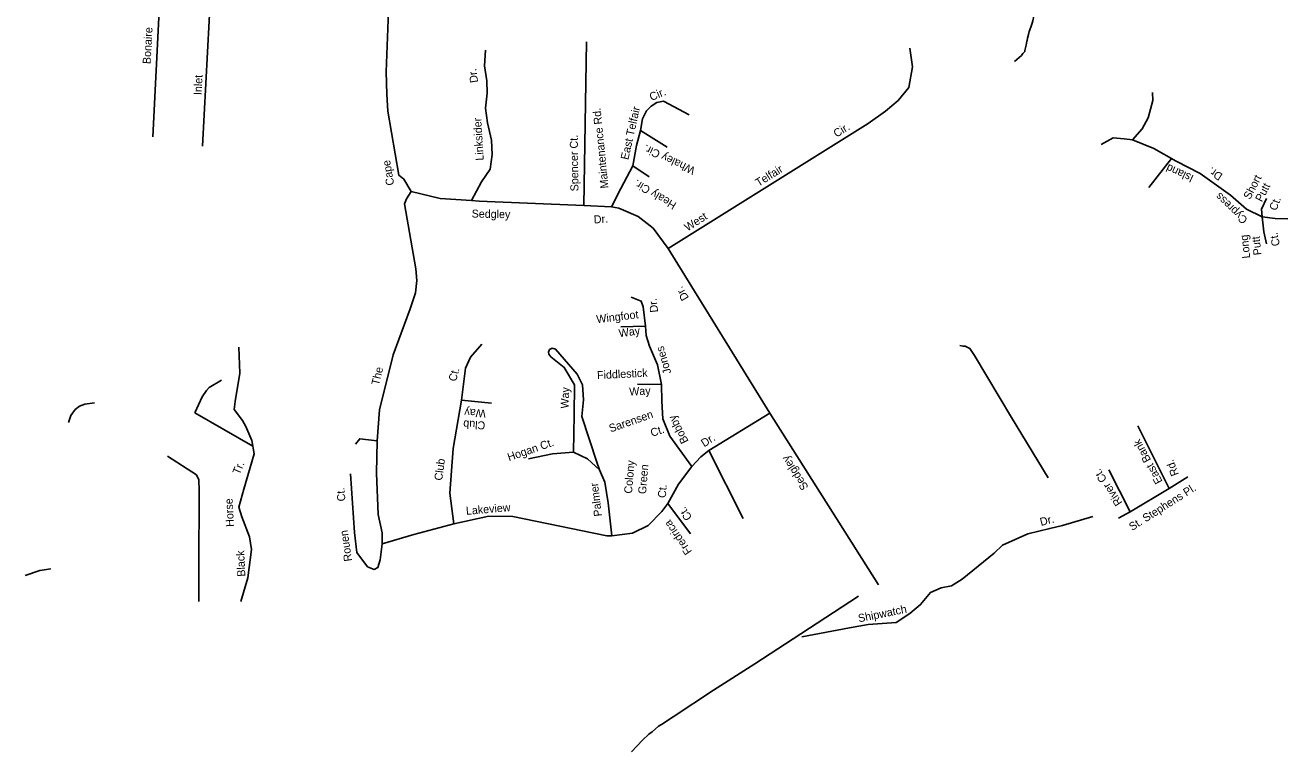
# Model space of a CAD drawing. Extents: x 2308163 to 2335412, y -96774 to 125428.
# Drawn here: x 2321552 to 2322199, y 33437 to 33809 of the extents above; entities that cross this region are included whole.
import ezdxf

# ---------------------------------------------------------------- set-up
doc = ezdxf.new("R2010")
doc.units = 0
doc.layers.add('Old_Level_10', color=7, linetype='Continuous')
doc.layers.add('Old_Level_35', color=7, linetype='Continuous')

msp = doc.modelspace()

# ---------------------------------------------------------------- linework, layer by layer
at = {"layer": 'Old_Level_35'}
for points in [[(2321642.5, 33747.31), (2321646.65, 33827.81), (2321648.99, 33855.68), (2321649.06, 33884.54), (2321651.46, 33914.24), (2321649.24, 33942.73), (2321649.43, 33961.51), (2321654.1, 33977.38), (2321655.96, 33991.52), (2321656.22, 34012.13)], [(2321616.99, 33752.13), (2321628.75, 33986.96), (2321626.26, 34007.67)], [(2321749.41, 33724.04), (2321745.7, 33730.45), (2321743.15, 33732.37), (2321737.47, 33765.29), (2321736.99, 33773.95), (2321736.6, 33785.48), (2321737.52, 33812.15), (2321737.23, 33818.97), (2321736.24, 33835.76), (2321735.15, 33849.93), (2321735.68, 33857.51), (2321738.55, 33865), (2321744.59, 33872.91), (2321749.05, 33880.61), (2321753.08, 33891.2), (2321757.94, 33910.41), (2321762.81, 33930.14), (2321769.45, 33955.57), (2321775.01, 33979.99), (2321776.9, 33993.77)], [(2322065.1, 33801.57), (2322065.4, 33802.63), (2322065.82, 33804.5), (2322066.22, 33806.12), (2322067.03, 33808.34), (2322067.72, 33810.45), (2322068.12, 33811.58), (2322068.26, 33812.44), (2322068.4, 33813.18), (2322068.29, 33814.31), (2322068.45, 33815.56), (2322067.95, 33820.45), (2322067.15, 33828.73), (2322066.12, 33838.01), (2322065.7, 33841.15), (2322065.68, 33845.27), (2322065.55, 33850.14), (2322065.86, 33858.26), (2322066.29, 33871.01), (2322067.1, 33889.12), (2322067.59, 33901.88)], [(2322058.61, 33790.79), (2322062.18, 33793.82), (2322062.96, 33794.81), (2322063.59, 33795.55), (2322063.98, 33795.9), (2322063.99, 33796.41), (2322064.58, 33799.14), (2322064.98, 33801.13), (2322065.1, 33801.57)], [(2321787.49, 33796.55), (2321786.95, 33788.46), (2321788.26, 33780.82), (2321788.3, 33774.53), (2321787.51, 33766.71), (2321788.57, 33759.34), (2321790.61, 33750.37), (2321790.89, 33743.03), (2321789.84, 33735.47), (2321785.43, 33729.08), (2321780.38, 33719.46)], [(2321837.88, 33716.95), (2321839.25, 33800.84)], [(2321881.13, 33694.78), (2321983.68, 33758.95), (2321992.54, 33765.19), (2321999.02, 33770.72), (2322004.49, 33777.34), (2322006.43, 33788.01), (2322004.92, 33797.48)], [(2321852, 33716.21), (2321856.78, 33725.62), (2321862.94, 33737.19), (2321864.87, 33747.6), (2321866.97, 33755.38), (2321867.97, 33761.37), (2321869.94, 33765.49), (2321872.38, 33767.76), (2321875.33, 33769.75), (2321878.76, 33770.42), (2321891.88, 33763.42)], [(2322119.09, 33750.47), (2322124.06, 33756.13), (2322127.18, 33761.86), (2322129.61, 33770.79), (2322129.48, 33774.77)], [(2321866.97, 33755.38), (2321880.56, 33746.79)], [(2322103.08, 33748.1), (2322109.31, 33751.6), (2322114.86, 33751.14), (2322119.09, 33750.47), (2322130.08, 33746.11), (2322141.54, 33739.61), (2322153.8, 33733.36), (2322169.34, 33722.21), (2322177.58, 33715.03), (2322185.67, 33711.04), (2322185.28, 33715.03), (2322187.86, 33720.51)], [(2321862.94, 33737.19), (2321871.4, 33731.66)], [(2322127.53, 33726.04), (2322139.05, 33741.03)], [(2321749.41, 33724.04), (2321746.92, 33720.25), (2321746.05, 33717.66), (2321751.72, 33684.48), (2321752.29, 33678.44), (2321751.55, 33672.18), (2321748.91, 33663.89), (2321740.24, 33640.37), (2321733.24, 33612.12), (2321731.9, 33596.2), (2321731.6, 33579.72), (2321732.44, 33558.48), (2321734.47, 33548.99), (2321734.54, 33543.49), (2321733.47, 33535.15), (2321732.28, 33531.26), (2321730.42, 33530.28), (2321727.06, 33531.7), (2321721.55, 33538.96), (2321720.33, 33549.21), (2321718.22, 33579.39)], [(2321893.25, 33582.99), (2321897.88, 33588.07), (2321901.92, 33591.33), (2321933.24, 33610.41), (2321881.13, 33694.78), (2321873.37, 33705.26), (2321865.71, 33711.28), (2321855.91, 33715.55), (2321852, 33716.21), (2321837.88, 33716.95), (2321784.3, 33719.06), (2321780.38, 33719.46), (2321764.17, 33720.54), (2321749.41, 33724.04)], [(2322185.67, 33711.04), (2322186.47, 33703.32), (2322187.85, 33697.17)], [(2322185.67, 33711.04), (2322192.28, 33710.28), (2322198.72, 33710.01)], [(2321734.54, 33543.49), (2321750.68, 33548.17), (2321771.31, 33553.74), (2321789.26, 33557.57), (2321801.57, 33557.41), (2321837.21, 33550.1), (2321849.69, 33547.58), (2321852.31, 33547.49), (2321862.84, 33548.96), (2321870.84, 33552.87), (2321877.89, 33559.96), (2321880.91, 33564.04), (2321886.4, 33574.06), (2321893.25, 33582.99), (2321882, 33598.56), (2321878.38, 33607.59), (2321877.9, 33616.51), (2321877.68, 33625.15), (2321875.67, 33635.17), (2321871.54, 33644.74), (2321869.9, 33650.29), (2321869.54, 33655.02), (2321868.31, 33665.01), (2321867.36, 33667.92), (2321862.19, 33669.93)], [(2321869.54, 33655.02), (2321856.95, 33654.67)], [(2321771.31, 33553.74), (2321769.28, 33569.36), (2321770.86, 33592.34), (2321775.12, 33617.07), (2321777.26, 33633.49), (2321779.81, 33639.16), (2321785.54, 33645.77)], [(2321662.08, 33513.8), (2321665.72, 33525.93), (2321667.6, 33540.53), (2321666.45, 33546.98), (2321662.67, 33557.19), (2321661.01, 33562.29), (2321663.62, 33571.36), (2321668.83, 33589.51), (2321667.69, 33596.42), (2321664.62, 33603.63), (2321663, 33606.66), (2321658.61, 33612.31), (2321659.21, 33616.42), (2321661.55, 33631), (2321661.09, 33644.3)], [(2321832.62, 33590.47), (2321833.02, 33609.57), (2321833.03, 33625.02), (2321827.83, 33633.84), (2321820.95, 33639.31), (2321819.95, 33640.65), (2321819.72, 33641.71), (2321820.29, 33643), (2321821.62, 33643.74), (2321823.44, 33643.15), (2321834.53, 33630.47), (2321837.22, 33624.87), (2321837.74, 33617.26), (2321836.92, 33608.65), (2321844.5, 33585.35), (2321845.93, 33581.38)], [(2322075.85, 33577.27), (2322057.2, 33608.23), (2322038.09, 33639.95), (2322035.79, 33643.65), (2322034.8, 33644.15), (2322033.45, 33644.68), (2322032.2, 33644.84), (2322030.58, 33645.14)], [(2321638.5, 33610.65), (2321642.3, 33618.72), (2321644.5, 33621.98), (2321645.81, 33623.61), (2321652.12, 33627.33)], [(2321877.68, 33625.15), (2321865.37, 33625.32)], [(2321573.79, 33605.57), (2321574.96, 33609.18), (2321577.19, 33612.29), (2321579.44, 33613.94), (2321582.15, 33615.1), (2321587.03, 33615.72)], [(2321775.12, 33617.07), (2321790.52, 33615.49)], [(2321638.5, 33610.65), (2321668.17, 33593.52)], [(2321933.24, 33610.41), (2321988.87, 33522.43)], [(2322121.84, 33603.92), (2322137.98, 33571.8), (2322147.48, 33577.84)], [(2321731.9, 33596.2), (2321723.03, 33597.29), (2321720.84, 33594.49)], [(2321624.45, 33588.42), (2321639.35, 33578.84), (2321640.52, 33576.25), (2321640.75, 33570.71), (2321640.62, 33530.74), (2321640.6, 33513.87)], [(2321852.31, 33547.49), (2321850.33, 33564.47), (2321848.6, 33575), (2321845.93, 33581.38), (2321839.84, 33587.08), (2321832.62, 33590.47), (2321821.85, 33589.54), (2321809.45, 33587.08)], [(2321901.92, 33591.33), (2321919.58, 33556.43)], [(2322117.92, 33559.76), (2322106.99, 33581.35)], [(2322137.98, 33571.8), (2322117.92, 33559.76), (2322111.97, 33556.52)], [(2321880.91, 33564.04), (2321892.59, 33548.46)], [(2321949.68, 33495.81), (2321974.04, 33500.27), (2321983.65, 33502.06), (2321998.02, 33503.16), (2322005.08, 33507.69), (2322010.55, 33512.27), (2322015.54, 33518.47), (2322021.04, 33520.93), (2322026.38, 33521.81), (2322031.81, 33525.33), (2322048.19, 33538.56), (2322052.57, 33542.65), (2322065.52, 33548.57), (2322076.76, 33551.36), (2322083.18, 33552.73), (2322098.74, 33557.5)], [(2321551.57, 33527.19), (2321558.97, 33529.79), (2321564.69, 33530.54)], [(2321978.76, 33516.57), (2321949.16, 33497.23), (2321925.52, 33481.93), (2321904.43, 33468.32), (2321883.72, 33454.68), (2321877.63, 33450.7), (2321876.22, 33449.85), (2321872.91, 33447.07), (2321871.24, 33445.85), (2321867.91, 33442.68), (2321862.35, 33436.81)]]:
    msp.add_lwpolyline(points, dxfattribs=at)

# ---------------------------------------------------------------- texts
at = {"layer": 'Old_Level_10'}
for s, rotation, p in [('Bonaire', 86.85287, (2321615.8, 33789.32)), ('Inlet', 87.81616, (2321642.04, 33773.44)), ('Dr.', 98.31149, (2321783.74, 33780.09)), ('Cir.', 22.8854, (2321872.55, 33770.41)), ('Maintenance Rd.', 95.70483, (2321850.57, 33725.84)), ('East Telfair ', 77.27677, (2321860.67, 33740.05)), ('Linksider', 93.46845, (2321786.6, 33740.04)), ('Cir.', 31.76923, (2321967.43, 33751.64)), ('Spencer Ct.', 90.73245, (2321835.14, 33724.16)), ('Whaley Cir.', 154.835, (2321895.36, 33736.21)), ('Cape', 99.96283, (2321740.76, 33727.52)), ('Telfair', 31.80691, (2321927.43, 33726.44)), (' Island ', 155.20343, (2322152.23, 33731.56)), ('Dr.', 146.86381, (2322165.69, 33732.81)), ('Healy Cir.', 149.12092, (2321885.74, 33718.08)), ('Short', 62.50556, (2322179.37, 33719.64)), ('Cypress', 136.19916, (2322178.51, 33709.9)), ('Putt', 62.50556, (2322185.43, 33718.41)), ('Ct.', 68.66812, (2322192.83, 33713.92)), ('Sedgley', 358.97939, (2321780.37, 33710.71)), ('Dr.', 3.77205, (2321843.12, 33707.64)), ('West', 32.36433, (2321891.02, 33703.53)), ('Long', 95.97678, (2322179.51, 33689.94)), ('Putt', 95.97678, (2322185.31, 33691.6)), ('Ct.', 101.76918, (2322194.78, 33696.5)), ('Dr.', 121.02009, (2321891.88, 33669.58)), ('Dr.', 96.5311, (2321876.01, 33662.25)), ('Wingfoot ', 6.88756, (2321844.57, 33656.53)), ('Way', 8.30907, (2321856.11, 33649.29)), ('Jones', 106.32219, (2321882.75, 33631.1)), ('The ', 76.32698, (2321732.88, 33624.42)), ('Ct.', 75.06851, (2321772.36, 33626.38)), ('Fiddlestick', 2.83826, (2321844.77, 33627.84)), ('Way', 87.71185, (2321830.04, 33612.71)), ('Way', 2.83826, (2321861.25, 33619.42)), ('Way', 176.69665, (2321787.74, 33612.18)), ('Club', 176.69665, (2321787.48, 33606.09)), ('Sarensen', 19.22892, (2321851.63, 33600.49)), ('Bobby', 117.11451, (2321891.68, 33596.02)), ('Ct.', 19.22892, (2321872.88, 33598.2)), ('Hogan Ct.', 19.00328, (2321799.55, 33585.76)), ('Dr.', 32.30181, (2321899.59, 33592.86)), ('East Bank', 118.32588, (2322134.69, 33575.42)), ('Sedgley', 122.91116, (2321953.22, 33572.55)), ('Tr.', 66.88351, (2321661.39, 33578.56)), ('Club ', 82.31385, (2321765.24, 33575.66)), ('Colony', 85.32775, (2321862.57, 33569.04)), ('Green ', 85.32775, (2321869.75, 33568.8)), ('River Ct.', 123.40587, (2322114.13, 33564.5)), ('Rd.', 110.76451, (2322142.96, 33579.06)), ('Palmer', 97.01727, (2321847.23, 33557.69)), ('Ct.', 94.67328, (2321715.71, 33565.35)), ('Ct.', 85.32775, (2321879.88, 33566.81)), ('St. Stephens Pl.', 32.47615, (2322118.97, 33549.97)), ('Horse', 92.96596, (2321658.59, 33552.21)), ('Lakeview', 4.75025, (2321777.64, 33558.27)), ('Ct.', 124.48233, (2321893.6, 33557.05)), ('Fredrica', 124.48233, (2321893.5, 33539.51)), ('Dr.', 14.48431, (2322072.27, 33552.56)), ('Rouen', 98.32171, (2321719.11, 33534.68)), ('Black', 92.66996, (2321664.41, 33526.67)), ('Shipwatch', 11.39025, (2321978.91, 33503.14))]:
    msp.add_text(s, height=4.101, rotation=rotation, dxfattribs=at).set_placement(p)

doc.saveas('drawing.dxf')
